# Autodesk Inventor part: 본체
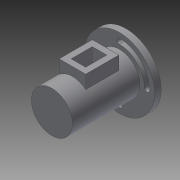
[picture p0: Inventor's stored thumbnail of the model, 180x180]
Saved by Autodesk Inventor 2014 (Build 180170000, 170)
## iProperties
Created: 2017-05
Part Number: 본체
Material: Generic
Document SubType Name: Modeling
Designer: Administrator
Density: 1 g/cm^3
Appearance: Default
Author: Administrator
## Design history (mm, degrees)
sketch "스케치1"
  geometry: C1 r 1346.2 at (0, 0); 1 further point
  constraints: 1 centre point, 1 coincident
  dimensions: "d0" = 2692.4 diameter of C1
extrude "돌출1" new body sketch "스케치1" distance "d1" = 254; taper "d2" = 0 deg
sketch "스케치2"
  geometry: C1 r 1346.2 at (0, 0) reference; C2 r 787.4 at (0, 0)
  constraints: 1 centre point, 1 coincident
  dimensions: "d3" = 1574.8 diameter of C2
extrude "돌출2" join sketch "스케치2" distance "d4" = 76.2; taper "d5" = 0 deg
sketch "스케치3"
  geometry: C1 r 1346.2 at (0, 0) reference; C2 r 787.4 at (0, 0)
  constraints: 1 centre point, 1 coincident
  dimensions: "d6" = 1574.8 diameter of C2
extrude "돌출3" join sketch "스케치3" distance "d7" = 2590.8; taper "d8" = 0 deg
sketch "스케치4"
  geometry: L1 (-1282.325, 1422.4)-(1282.325, 1422.4); L2 (0, 0)-(0, 3368.241); L3 (787.4, 2844.8)-(-787.4, 2844.8) reference; L4 (-508, 2057.4)-(508, 2057.4); L5 (508, 2057.4)-(508, 787.4); L6 (508, 787.4)-(-508, 787.4); L7 (-508, 787.4)-(-508, 2057.4); L8 (508, 787.4)-(-508, 2057.4); 1 further point
  constraints: 14 end point, 2 horizontal, 2 midpoint, 2 parallel, 2 perpendicular, 1 point on line
  dimensions: "d9" = 1422.4 distance between parallel lines of L3 L1; "d10" = 1016 distance of L4.start L4.end; "d11" = 1270 distance of L4.end L5.end
extrude "돌출4" join sketch "스케치4" distance "d12" = 1117.6; taper "d13" = 0 deg
sketch "스케치5"
  geometry: L1 (-787.4, -76.2)-(787.4, -76.2) reference; L2 (558.8, -76.2)-(406.4, 279.4); L3 (406.4, 279.4)-(-406.4, 279.4); L4 (-406.4, 279.4)-(-558.8, -76.2); L5 (0, 0)-(0, -402.079); L6 (0, 0)-(0, 279.4); L7 (406.4, 279.4)-(0, 279.4); L8 (0, -76.2)-(0, 279.4); L9 (0, -76.2)-(558.8, -76.2)
  constraints: 16 end point, 3 collinear, 3 point on line, 2 midpoint, 1 parallel, 1 perpendicular, 1 other
  dimensions: "d14" = 355.6 distance between parallel lines of L1 L3; "d15" = 1117.6 distance of L2.start L4.end; "d16" = 812.8 distance of L2.end L3.end
revolve "회전1" sketch "스케치5" stored, may be unused: angle "d17" = 90 deg
sketch "스케치6"
  geometry: C1 r 406.4 at (0, 0) reference; C2 r 317.5 at (0, 0)
  constraints: 1 centre point, 1 coincident
  dimensions: "d18" = 635 diameter of C2
extrude "돌출5" cut sketch "스케치6" distance "d19" = 185.42; taper "d20" = 0 deg
sketch "스케치7"
  geometry: C1 r 317.5 at (0, 0) reference; C2 r 254 at (0, 0)
  constraints: 1 centre point, 1 coincident
  dimensions: "d21" = 508 diameter of C2
extrude "돌출6" cut sketch "스케치7" distance "d22" = 68.58; taper "d23" = 0 deg
node "작업 평면1"
sketch "스케치9"
  geometry: C1 r 609.6 at (0, 0); 1 further point
  constraints: 1 centre point, 1 coincident
  dimensions: "d32" = 1219.2 diameter of C1
extrude "돌출7" cut sketch "스케치9" distance "d33" = 76.2; taper "d34" = 0 deg
node "작업 평면2"
sketch "스케치10"
  geometry: C1 r 508 at (0, 0); 1 further point
  constraints: 1 centre point, 1 coincident
  dimensions: "d36" = 1016 diameter of C1
extrude "돌출8" cut sketch "스케치10" distance "d37" = 228.6; taper "d38" = 0 deg
node "작업 평면3"
sketch "스케치11"
  geometry: C1 r 444.5 at (0, 0); 1 further point
  constraints: 1 centre point, 1 coincident
  dimensions: "d40" = 889 diameter of C1
extrude "돌출9" cut sketch "스케치11" distance "d41" = 82.55; taper "d42" = 0 deg
node "작업 평면4"
sketch "스케치12"
  geometry: C1 r 469.9 at (0, 0); 1 further point
  constraints: 1 centre point, 1 coincident
  dimensions: "d44" = 939.8 diameter of C1
extrude "돌출10" cut sketch "스케치12" distance "d45" = 44.45; taper "d46" = 0 deg
node "작업 평면5"
sketch "스케치13"
  geometry: C1 r 444.5 at (0, 0); 1 further point
  constraints: 1 centre point, 1 coincident
  dimensions: "d48" = 889 diameter of C1
extrude "돌출11" cut sketch "스케치13" distance "d49" = 279.4; taper "d50" = 0 deg
node "작업 평면6"
sketch "스케치14"
  geometry: C1 r 660.4 at (0, 0); 1 further point
  constraints: 1 centre point, 1 coincident
  dimensions: "d52" = 1320.8 diameter of C1
extrude "돌출12" cut sketch "스케치14" distance "d53" = 965.2; taper "d54" = 0 deg
node "작업 평면7"
sketch "스케치15"
  geometry: C1 r 444.5 at (0, 0); 1 further point
  constraints: 1 centre point, 1 coincident
  dimensions: "d56" = 889 diameter of C1
extrude "돌출13" cut sketch "스케치15" distance "d57" = 279.4; taper "d58" = 0 deg
sketch "스케치16"
  geometry: C1 r 254 at (0, 0) reference; C2 r 419.1 at (0, 0)
  constraints: 1 centre point, 1 coincident
  dimensions: "d59" = 838.2 diameter of C2
extrude "돌출14" cut sketch "스케치16" distance "d60" = 127; taper "d61" = 0 deg
sketch "스케치17"
  geometry: L1 (-279.4, -1016)-(279.4, -1016); L2 (279.4, -1016)-(279.4, -1828.8); L3 (279.4, -1828.8)-(-279.4, -1828.8); L4 (-279.4, -1828.8)-(-279.4, -1016); L5 (279.4, -1828.8)-(-279.4, -1016); L6 (0, 0)-(0, -2328.088); L7 (-1086.055, -1422.4)-(1159.752, -1422.4); L8 (-787.4, -2844.8)-(787.4, -2844.8) reference; 1 further point
  constraints: 14 end point, 3 parallel, 2 perpendicular, 2 point on line, 1 horizontal, 1 midpoint
  dimensions: "d62" = 1422.4 distance between parallel lines of L8 L7; "d63" = 558.8 distance of L2.end L3.end; "d64" = 812.8 distance of L3.end L1.start
extrude "돌출15" cut sketch "스케치17" stored distance "d65" = 127; taper "d66" = 0 deg
sketch "스케치18"
  geometry: L1 (0, 0)-(2136.06, 0); L2 (0, 0)-(0, 2217.636); L3 (0, 0)-(0, -1590.826); L4 (0, 0)-(-1756.972, 0); C1 r 1346.2 at (0, 0) reference; A1 r 1054.1 centre (0, 0) between (-1049.204, 101.482) and (-101.482, 1049.204); A2 r 101.6 centre (1054.1, 0) between (952.5, 0) and (1155.7, 0); A3 r 101.6 centre (-1054.1, 0) between (-1155.7, 0) and (-952.5, 0); A4 r 101.6 centre (0, 1054.1) between (0, 1155.7) and (0, 952.5); A5 r 101.6 centre (0, -1054.1) between (0, -1155.7) and (0, -952.5); A6 r 952.5 centre (0, 0) between (-952.5, 0) and (0, -952.5); A7 r 952.5 centre (0, 0) between (952.5, 0) and (0, 952.5); A8 r 1155.7 centre (0, 0) between (-1155.7, 0) and (0, -1155.7); A9 r 1155.7 centre (0, 0) between (1155.7, 0) and (0, 1155.7)
  constraints: 24 point on circle, 9 centre point, 8 end point, 8 point on line, 3 coincident, 2 perpendicular, 1 collinear, 1 horizontal
  dimensions: "d69" = 2108.2 diameter of A1; "d70" = 101.6 radius of A2; "d71" = 101.6 radius of A3; "d72" = 101.6 radius of A4; "d73" = 101.6 radius of A5
extrude "돌출16" cut sketch "스케치18" stored distance "d74" = 127; taper "d75" = 0 deg
node "솔리드1"
other parameters: "d31" = -228.6, "d35" = -304.8, "d39" = -533.4, "d43" = -660.4, "d47" = -660.4, "d51" = -939.8, "d55" = -1905, "d67" = 2311.4, "d68" = 1905
